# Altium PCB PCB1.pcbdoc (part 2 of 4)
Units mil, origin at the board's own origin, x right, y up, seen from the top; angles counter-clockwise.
Board outline 4701.34 x 4268.46 mil, 2 copper layers (Top Layer, Bottom Layer); 341 components, 58 nets, 1384 pads, 312 vias.
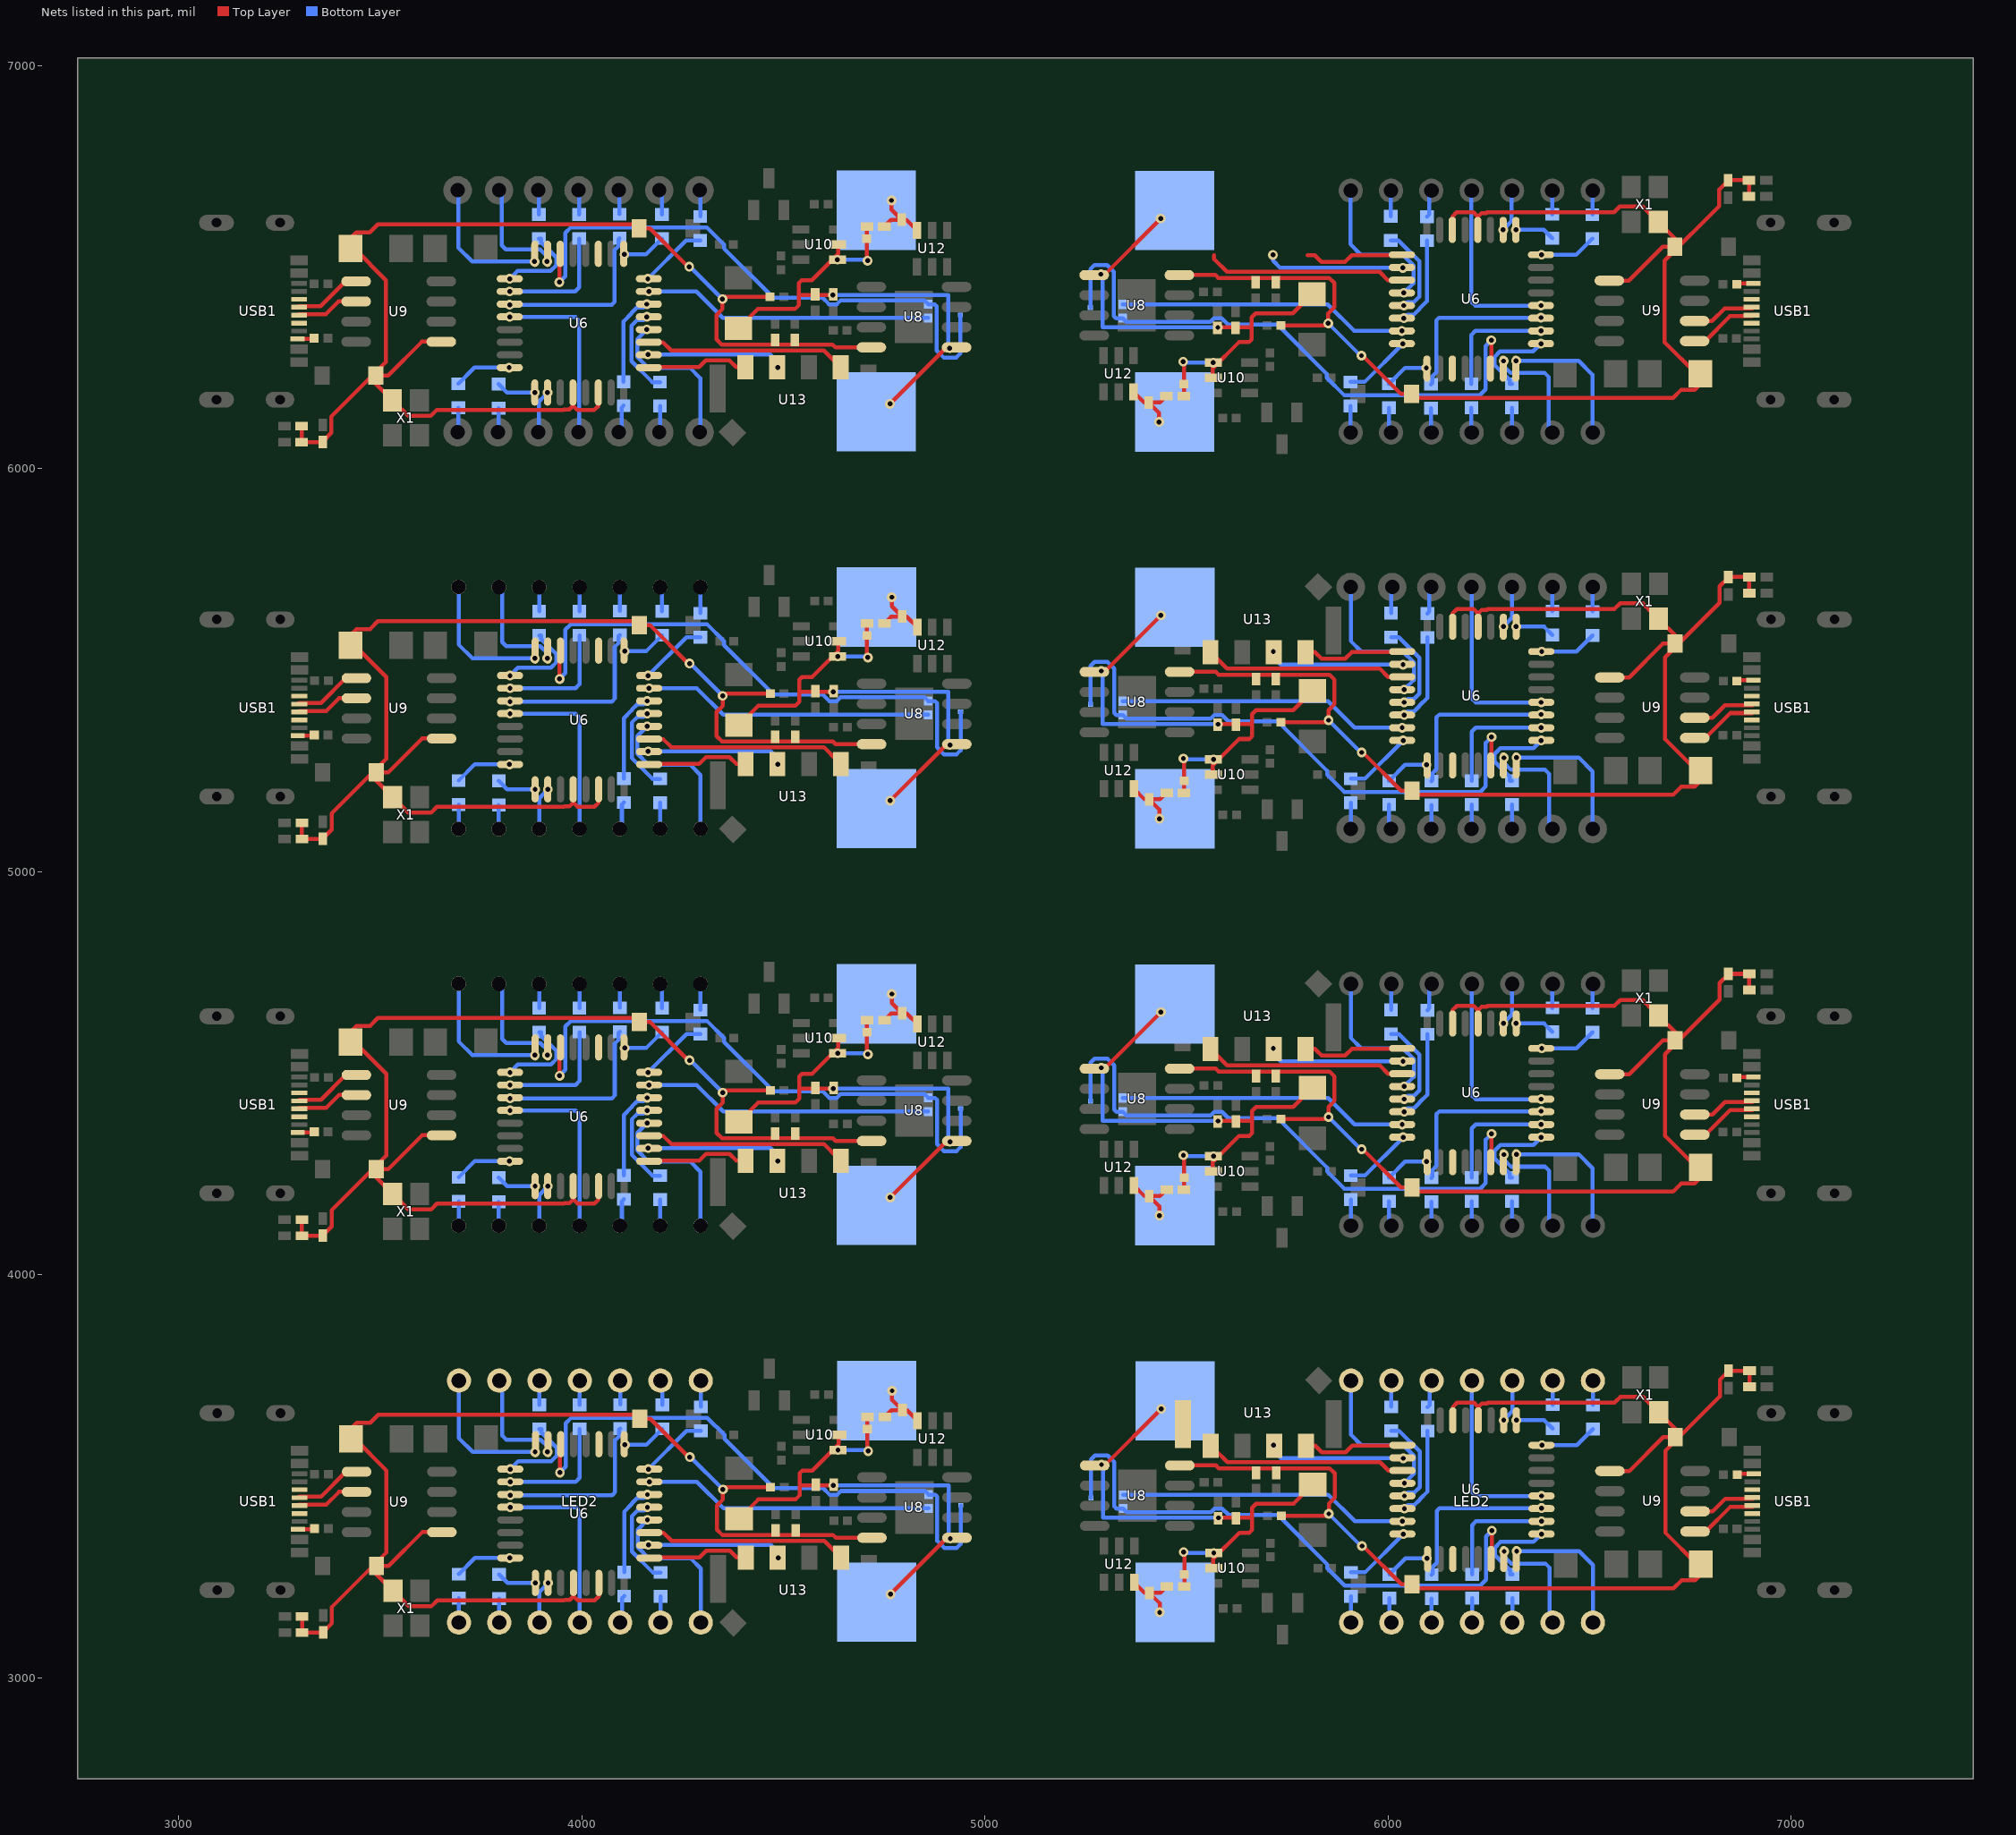
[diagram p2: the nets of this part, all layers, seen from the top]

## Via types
v1: diameter 24.02, hole 12.01, Top Layer to Bottom Layer, 312 vias

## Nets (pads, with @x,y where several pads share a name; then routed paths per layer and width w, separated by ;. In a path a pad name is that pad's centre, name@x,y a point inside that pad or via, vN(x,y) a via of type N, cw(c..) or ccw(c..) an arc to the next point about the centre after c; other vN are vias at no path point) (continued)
$1N14266: C24.2 C28.1 pad.73 pad.74 pad.75 pad.76 pad.77 pad.78 pad.79 pad.80 pad.81 pad.82 pad.83 pad.84 pad.85 pad.86 pad.88 pad.89 pad.91 pad.92 pad.93 pad.94 pad.95 pad.96 pad.97 pad.98 pad.100 pad.101 pad.102 pad.103 pad.104 pad.105 pad.106 pad.108 pad.124 pad.126 U12.6 | length 1259.3
  Top Layer w10: C28.1@4750.57,6600.59 4767.03,6617.05 C24.2@4794.11,6617.05 ; C28.1@4751.24,4632.09 4767.7,4648.55 C24.2@4794.78,4648.55 ; C28.1@4751.24,5616.34 4767.7,5632.8 C24.2@4794.78,5632.8 ; C28.1@4751.91,3647.83 4768.37,3664.29 C24.2@4795.45,3664.29 ; v1(4768.57,6665.07) 4768.57,6642.59 C24.2@4794.11,6617.05 ; v1(4769.24,4696.56) 4769.24,4674.09 C24.2@4794.78,4648.55 ; v1(4769.24,5680.81) 4769.24,5658.34 C24.2@4794.78,5632.8 ; v1(4769.91,3712.31) 4769.91,3689.83 C24.2@4795.45,3664.29 ; U12.6@4831.71,6590.83 4805.49,6617.05 C24.2@4794.11,6617.05 ; U12.6@4832.38,4622.33 4806.16,4648.55 C24.2@4794.78,4648.55 ; U12.6@4832.38,5606.58 4806.16,5632.8 C24.2@4794.78,5632.8 ; U12.6@4833.05,3638.07 4806.83,3664.29 C24.2@4795.45,3664.29 ; U12.6@5369.12,6189.84 5395.34,6163.62 C24.2@5406.72,6163.62 ; U12.6@5369.78,4221.34 5396,4195.12 C24.2@5407.38,4195.12 ; U12.6@5369.78,5205.59 5396,5179.37 C24.2@5407.38,5179.37 ; U12.6@5370.45,3237.09 5396.67,3210.87 C24.2@5408.05,3210.87 ; v1(5432.26,6115.61) 5432.26,6138.08 C24.2@5406.72,6163.62 ; v1(5432.92,4147.1) 5432.92,4169.58 C24.2@5407.38,4195.12 ; v1(5432.92,5131.35) 5432.92,5153.83 C24.2@5407.38,5179.37 ; v1(5433.59,3162.85) 5433.59,3185.32 C24.2@5408.05,3210.87 ; C28.1@5450.26,6180.08 5433.8,6163.62 C24.2@5406.72,6163.62 ; C28.1@5450.92,4211.58 5434.46,4195.12 C24.2@5407.38,4195.12 ; C28.1@5450.92,5195.83 5434.46,5179.37 C24.2@5407.38,5179.37 ; C28.1@5451.59,3227.33 5435.13,3210.87 C24.2@5408.05,3210.87
$1N25004: R39.1 | length 573.8
  Bottom Layer w10: R39.1@4194.11,6155.25 4194.11,6090.59 4199.11,6085.59 ; R39.1@4194.78,4186.75 4194.78,4122.09 4199.78,4117.09 ; R39.1@4194.78,5171 4194.78,5106.34 4199.78,5101.34 ; R39.1@4195.45,3202.49 4195.45,3137.83 4200.45,3132.83 ; 6001.72,6695.08 6006.72,6690.08 R39.1@6006.72,6625.42 ; 6002.38,4726.58 6007.38,4721.58 R39.1@6007.38,4656.92 ; 6002.38,5710.83 6007.38,5705.83 R39.1@6007.38,5641.17 ; 6003.05,3742.33 6008.05,3737.33 R39.1@6008.05,3672.67
$1N25008: R40.1 | length 532.8
  Bottom Layer w10: R40.1@3793.87,6150.02 3793.87,6090.83 3799.11,6085.59 ; R40.1@3794.54,4181.52 3794.54,4122.33 3799.78,4117.09 ; R40.1@3794.54,5165.77 3794.54,5106.58 3799.78,5101.34 ; R40.1@3795.21,3197.27 3795.21,3138.08 3800.45,3132.83 ; 6401.72,6695.08 6406.96,6689.84 R40.1@6406.96,6630.65 ; 6402.38,4726.58 6407.63,4721.34 R40.1@6407.63,4662.14 ; 6402.38,5710.83 6407.63,5705.59 R40.1@6407.63,5646.4 ; 6403.05,3742.33 6408.29,3737.08 R40.1@6408.29,3677.89
$1N25012: R41.1 | length 579.3
  Bottom Layer w10: 4099.11,6085.59 4099.11,6150.93 R41.1@4104.11,6155.93 ; 4099.78,4117.09 4099.78,4182.43 R41.1@4104.78,4187.43 ; 4099.78,5101.34 4099.78,5166.68 R41.1@4104.78,5171.68 ; 4100.45,3132.83 4100.45,3198.17 R41.1@4105.45,3203.17 ; R41.1@6096.72,6624.74 6101.72,6629.74 6101.72,6695.08 ; R41.1@6097.38,4656.24 6102.38,4661.24 6102.38,4726.58 ; R41.1@6097.38,5640.49 6102.38,5645.49 6102.38,5710.83 ; R41.1@6098.05,3671.99 6103.05,3676.99 6103.05,3742.33
$1N25014: R45.2 | length 445.3
  Bottom Layer w10: R45.2@4198.87,6630.02 4198.87,6685.35 4199.11,6685.59 ; R45.2@4199.54,4661.52 4199.54,4716.84 4199.78,4717.09 ; R45.2@4199.54,5645.77 4199.54,5701.1 4199.78,5701.34 ; R45.2@4200.21,3677.27 4200.21,3732.59 4200.45,3732.83 ; 6001.72,6095.08 6001.96,6095.32 R45.2@6001.96,6150.65 ; 6002.38,4126.58 6002.63,4126.82 R45.2@6002.63,4182.14 ; 6002.38,5110.83 6002.63,5111.07 R45.2@6002.63,5166.4 ; 6003.05,3142.33 6003.29,3142.57 R45.2@6003.29,3197.89
$1N25016: R46.2 | length 499.3
  Bottom Layer w10: R46.2@4294.11,6625.25 4294.11,6680.59 4299.11,6685.59 ; R46.2@4294.78,4656.75 4294.78,4712.09 4299.78,4717.09 ; R46.2@4294.78,5641 4294.78,5696.34 4299.78,5701.34 ; R46.2@4295.45,3672.49 4295.45,3727.83 4300.45,3732.83 ; 5901.72,6095.08 5906.72,6100.08 R46.2@5906.72,6155.42 ; 5902.38,4126.58 5907.38,4131.58 R46.2@5907.38,4186.92 ; 5902.38,5110.83 5907.38,5115.83 R46.2@5907.38,5171.17 ; 5903.05,3142.33 5908.05,3147.33 R46.2@5908.05,3202.67
$1N25022: R43.2 | length 461.9
  Bottom Layer w10: R43.2@3993.87,6630.02 3993.87,6680.35 3999.11,6685.59 ; R43.2@3994.54,4661.52 3994.54,4711.84 3999.78,4717.09 ; R43.2@3994.54,5645.77 3994.54,5696.1 3999.78,5701.34 ; R43.2@3995.21,3677.27 3995.21,3727.59 4000.45,3732.83 ; 6201.72,6095.08 6206.96,6100.32 R43.2@6206.96,6150.65 ; 6202.38,4126.58 6207.63,4131.82 R43.2@6207.63,4182.14 ; 6202.38,5110.83 6207.63,5116.07 R43.2@6207.63,5166.4 ; 6203.05,3142.33 6208.29,3147.57 R43.2@6208.29,3197.89
$1N25024: R42.2 | length 463.7
  Bottom Layer w10: R42.2@3893.87,6630.02 3893.87,6689.55 ; R42.2@3894.54,4661.52 3894.54,4711.84 3899.78,4717.09 ; R42.2@3894.54,5645.77 3894.54,5696.1 3899.78,5701.34 ; R42.2@3895.21,3677.27 3895.21,3727.59 3900.45,3732.83 ; 6301.72,6095.08 6306.96,6100.32 R42.2@6306.96,6150.65 ; 6302.38,4126.58 6307.63,4131.82 R42.2@6307.63,4182.14 ; 6302.38,5110.83 6307.63,5116.07 R42.2@6307.63,5166.4 ; 6303.05,3142.33 6308.29,3147.57 R42.2@6308.29,3197.89
$1N25046: R44.1 | length 539.3
  Bottom Layer w10: R44.1@3694.11,6150.93 3694.11,6090.59 3699.11,6085.59 ; R44.1@3694.78,4182.43 3694.78,4122.09 3699.78,4117.09 ; R44.1@3694.78,5166.68 3694.78,5106.34 3699.78,5101.34 ; R44.1@3695.45,3198.17 3695.45,3137.83 3700.45,3132.83 ; 6501.72,6695.08 6506.72,6690.08 R44.1@6506.72,6629.74 ; 6502.38,4726.58 6507.38,4721.58 R44.1@6507.38,4661.24 ; 6502.38,5710.83 6507.38,5705.83 R44.1@6507.38,5645.49 ; 6503.05,3742.33 6508.05,3737.33 R44.1@6508.05,3676.99
$1N26871: R57.2 | length 453.8
  Bottom Layer w10: R57.2@4094.11,6630.93 4094.11,6680.59 4099.11,6685.59 ; R57.2@4094.78,4662.43 4094.78,4712.09 4099.78,4717.09 ; R57.2@4094.78,5646.68 4094.78,5696.34 4099.78,5701.34 ; R57.2@4095.45,3678.17 4095.45,3727.83 4100.45,3732.83 ; 6101.72,6095.08 6106.72,6100.08 R57.2@6106.72,6149.74 ; 6102.38,4126.58 6107.38,4131.58 R57.2@6107.38,4181.24 ; 6102.38,5110.83 6107.38,5115.83 R57.2@6107.38,5165.49 ; 6103.05,3142.33 6108.05,3147.33 R57.2@6108.05,3196.99
$1N29845: R52.2 USB1.B5 | length 337.9
  Top Layer w10: USB1.B5@3295.2,6321.39 3295.3,6321.29 3337.25,6321.29 R52.2@3337.16,6321.39 ; USB1.B5@3295.87,4352.88 3295.96,4352.78 3337.92,4352.78 R52.2@3337.82,4352.88 ; USB1.B5@3295.87,5337.13 3295.96,5337.04 3337.92,5337.04 R52.2@3337.82,5337.13 ; USB1.B5@3296.53,3368.63 3296.63,3368.53 3338.59,3368.53 R52.2@3338.49,3368.63 ; R52.2@6863.67,6459.29 6863.57,6459.38 6905.53,6459.38 USB1.B5@6905.63,6459.29 ; R52.2@6864.34,4490.78 6864.24,4490.88 6906.2,4490.88 USB1.B5@6906.3,4490.78 ; R52.2@6864.34,5475.03 6864.24,5475.13 6906.2,5475.13 USB1.B5@6906.3,5475.03 ; R52.2@6865.01,3506.53 6864.91,3506.63 6906.87,3506.63 USB1.B5@6906.96,3506.53
$1N31822: LED2.13
$1N31824: LED2.9
$1N31826: LED2.12
$1N31828: LED2.5
$1N31830: LED2.4
$1N31832: LED2.8
$1N31834: LED2.2
$1N31836: LED2.1
$1N31838: LED2.3
+5V: C19.2 C20.2 C21.1 C25.2 C27.2 D5.1 D6.1 L6.1 R53.2 U6.4 U6.6 U8.4 U9.5 X1.3 | length 25770.4
  Top Layer w10: C25.2@3305.57,6105.59 C21.1@3305.57,6065.59 C27.2@3357.65,6065.59 3357.65,6066.79 3379.26,6088.41 3379.26,6129.11 3514.68,6264.53 3514.68,6467.32 L6.1@3436.41,6545.59 ; C25.2@3306.24,4137.09 C21.1@3306.24,4097.09 C27.2@3358.32,4097.09 3358.32,4098.29 3379.93,4119.9 3379.93,4160.61 3515.35,4296.03 3515.35,4498.81 L6.1@3437.08,4577.09 ; C25.2@3306.24,5121.34 C21.1@3306.24,5081.34 C27.2@3358.32,5081.34 3358.32,5082.54 3379.93,5104.16 3379.93,5144.86 3515.35,5280.28 3515.35,5483.06 L6.1@3437.08,5561.34 ; C25.2@3306.91,3152.83 C21.1@3306.91,3112.83 C27.2@3358.99,3112.83 3358.99,3114.04 3380.6,3135.65 3380.6,3176.36 3516.02,3311.78 3516.02,3514.56 L6.1@3437.75,3592.83 ; L6.1@3426.41,6545.59 3426.41,6571.36 3441.02,6585.98 3474.5,6585.98 3494.11,6605.59 4132.48,6605.59 D5.1@4142.48,6595.59 4169.11,6595.59 4264.11,6500.59 v1(4266.86,6500.59) ; L6.1@3427.08,4577.09 3427.08,4602.86 3441.69,4617.47 3475.16,4617.47 3494.78,4637.09 4133.15,4637.09 D5.1@4143.15,4627.09 4169.78,4627.09 4264.78,4532.09 v1(4267.53,4532.09) ; L6.1@3427.08,5561.34 3427.08,5587.11 3441.69,5601.72 3475.16,5601.72 3494.78,5621.34 4133.15,5621.34 D5.1@4143.15,5611.34 4169.78,5611.34 4264.78,5516.34 v1(4267.53,5516.34) ; L6.1@3427.75,3592.83 3427.75,3618.61 3442.36,3633.22 3475.83,3633.22 3495.45,3652.83 4133.82,3652.83 D5.1@4143.82,3642.83 4170.45,3642.83 4265.45,3547.83 v1(4268.2,3547.83) ; U9.5@3651.89,6314.53 3603.66,6314.53 3519.72,6230.59 3485.74,6230.59 3485.74,6213.81 X1.3@3530.65,6168.9 3531.68,6168.9 3553.96,6146.62 3554.17,6146.62 3562.97,6137.82 3562.97,6136.79 3569.4,6130.36 3625.75,6130.36 3640.52,6145.13 3955.09,6145.13 3956.58,6146.62 3969.11,6146.62 3978.36,6155.87 ; U9.5@3652.55,4346.02 3604.33,4346.02 3520.39,4262.09 3486.41,4262.09 3486.41,4245.3 X1.3@3531.31,4200.4 3532.35,4200.4 3554.62,4178.12 3554.84,4178.12 3563.64,4169.32 3563.64,4168.29 3570.07,4161.85 3626.42,4161.85 3641.18,4176.62 3955.75,4176.62 3957.25,4178.12 3969.78,4178.12 3979.03,4187.37 ; U9.5@3652.55,5330.28 3604.33,5330.28 3520.39,5246.34 3486.41,5246.34 3486.41,5229.55 X1.3@3531.31,5184.65 3532.35,5184.65 3554.62,5162.37 3554.84,5162.37 3563.64,5153.57 3563.64,5152.54 3570.07,5146.11 3626.42,5146.11 3641.18,5160.87 3955.75,5160.87 3957.25,5162.37 3969.78,5162.37 3979.03,5171.62 ; U9.5@3653.22,3361.77 3604.99,3361.77 3521.06,3277.83 3487.08,3277.83 3487.08,3261.05 X1.3@3531.98,3216.14 3533.01,3216.14 3555.29,3193.87 3555.51,3193.87 3564.31,3185.07 3564.31,3184.03 3570.74,3177.6 3627.08,3177.6 3641.85,3192.37 3956.42,3192.37 3957.92,3193.87 3970.45,3193.87 3979.7,3203.12 ; U6.4@3978.36,6188.59 3978.36,6155.87 ; U6.4@3979.03,4220.09 3979.03,4187.37 ; U6.4@3979.03,5204.34 3979.03,5171.62 ; U6.4@3979.7,3235.83 3979.7,3203.12 ; U6.6@4041.35,6188.59 4041.35,6155.59 4030.89,6145.13 3989.11,6145.13 3978.36,6155.87 ; U6.6@4042.02,4220.09 4042.02,4187.09 4031.56,4176.62 3989.78,4176.62 3979.03,4187.37 ; U6.6@4042.02,5204.34 4042.02,5171.34 4031.56,5160.87 3989.78,5160.87 3979.03,5171.62 ; U6.6@4042.69,3235.83 4042.69,3202.83 4032.23,3192.37 3990.45,3192.37 3979.7,3203.12 ; R53.2@4467.07,6425.59 4354.11,6425.59 v1(4349.11,6420.59) 4349.11,6395.59 4334.11,6380.59 4334.11,6320.59 4347.03,6307.67 4622.03,6307.67 4629.11,6300.59 U8.4@4718.5,6300.59 ; R53.2@4467.74,4457.09 4354.78,4457.09 v1(4349.78,4452.09) 4349.78,4427.09 4334.78,4412.09 4334.78,4352.09 4347.7,4339.17 4622.7,4339.17 4629.78,4332.09 U8.4@4719.17,4332.09 ; R53.2@4467.74,5441.34 4354.78,5441.34 v1(4349.78,5436.34) 4349.78,5411.34 4334.78,5396.34 4334.78,5336.34 4347.7,5323.42 4622.7,5323.42 4629.78,5316.34 U8.4@4719.17,5316.34 ; R53.2@4468.41,3472.83 4355.45,3472.83 v1(4350.45,3467.83) 4350.45,3442.83 4335.45,3427.83 4335.45,3367.83 4348.36,3354.92 4623.36,3354.92 4630.45,3347.83 U8.4@4719.84,3347.83 ; U8.4@5482.33,6480.08 5571.72,6480.08 5578.8,6473 5853.8,6473 5866.72,6460.08 5866.72,6400.08 5851.72,6385.08 v1(5851.72,6360.08) 5846.72,6355.08 R53.2@5733.76,6355.08 ; U8.4@5482.99,4511.58 5572.38,4511.58 5579.47,4504.49 5854.47,4504.49 5867.38,4491.58 5867.38,4431.58 5852.38,4416.58 v1(5852.38,4391.58) 5847.38,4386.58 R53.2@5734.42,4386.58 ; U8.4@5482.99,5495.83 5572.38,5495.83 5579.47,5488.75 5854.47,5488.75 5867.38,5475.83 5867.38,5415.83 5852.38,5400.83 v1(5852.38,5375.83) 5847.38,5370.83 R53.2@5734.42,5370.83 ; U8.4@5483.66,3527.33 5573.05,3527.33 5580.14,3520.24 5855.14,3520.24 5868.05,3507.33 5868.05,3447.33 5853.05,3432.33 v1(5853.05,3407.33) 5848.05,3402.33 R53.2@5735.09,3402.33 ; v1(5933.96,6280.08) 5936.72,6280.08 6031.72,6185.08 D5.1@6058.35,6185.08 6068.35,6175.08 6706.72,6175.08 6726.33,6194.7 6759.8,6194.7 6774.42,6209.31 L6.1@6774.42,6235.08 ; v1(5934.63,4311.58) 5937.38,4311.58 6032.38,4216.58 D5.1@6059.01,4216.58 6069.01,4206.58 6707.38,4206.58 6727,4226.19 6760.47,4226.19 6775.08,4240.81 L6.1@6775.08,4266.58 ; v1(5934.63,5295.83) 5937.38,5295.83 6032.38,5200.83 D5.1@6059.01,5200.83 6069.01,5190.83 6707.38,5190.83 6727,5210.44 6760.47,5210.44 6775.08,5225.06 L6.1@6775.08,5250.83 ; v1(5935.3,3327.33) 5938.05,3327.33 6033.05,3232.33 D5.1@6059.68,3232.33 6069.68,3222.33 6708.05,3222.33 6727.67,3241.94 6761.14,3241.94 6775.75,3256.55 L6.1@6775.75,3282.33 ; U6.6@6159.47,6592.08 6159.47,6625.08 6169.94,6635.55 6211.72,6635.55 6222.46,6624.8 ; U6.6@6160.14,4623.58 6160.14,4656.58 6170.6,4667.04 6212.38,4667.04 6223.13,4656.29 ; U6.6@6160.14,5607.83 6160.14,5640.83 6170.6,5651.29 6212.38,5651.29 6223.13,5640.55 ; U6.6@6160.81,3639.33 6160.81,3672.33 6171.27,3682.79 6213.05,3682.79 6223.8,3672.04 ; U6.4@6222.46,6592.08 6222.46,6624.8 ; U6.4@6223.13,4623.58 6223.13,4656.29 ; U6.4@6223.13,5607.83 6223.13,5640.55 ; U6.4@6223.8,3639.33 6223.8,3672.04 ; U9.5@6548.94,6466.15 6597.17,6466.15 6681.11,6550.08 6715.09,6550.08 6715.09,6566.87 X1.3@6670.18,6611.77 6669.15,6611.77 6646.87,6634.05 6646.66,6634.05 6637.86,6642.85 6637.86,6643.88 6631.42,6650.32 6575.08,6650.32 6560.31,6635.55 6245.74,6635.55 6244.24,6634.05 6231.72,6634.05 6222.46,6624.8 ; U9.5@6549.61,4497.64 6597.84,4497.64 6681.77,4581.58 6715.75,4581.58 6715.75,4598.36 X1.3@6670.85,4643.27 6669.82,4643.27 6647.54,4665.55 6647.32,4665.55 6638.52,4674.34 6638.52,4675.38 6632.09,4681.81 6575.75,4681.81 6560.98,4667.04 6246.41,4667.04 6244.91,4665.55 6232.38,4665.55 6223.13,4656.29 ; U9.5@6549.61,5481.89 6597.84,5481.89 6681.77,5565.83 6715.75,5565.83 6715.75,5582.61 X1.3@6670.85,5627.52 6669.82,5627.52 6647.54,5649.8 6647.32,5649.8 6638.52,5658.6 6638.52,5659.63 6632.09,5666.06 6575.75,5666.06 6560.98,5651.29 6246.41,5651.29 6244.91,5649.8 6232.38,5649.8 6223.13,5640.55 ; U9.5@6550.28,3513.39 6598.51,3513.39 6682.44,3597.33 6716.42,3597.33 6716.42,3614.11 X1.3@6671.52,3659.02 6670.49,3659.02 6648.21,3681.29 6647.99,3681.29 6639.19,3690.09 6639.19,3691.12 6632.76,3697.56 6576.42,3697.56 6561.65,3682.79 6247.08,3682.79 6245.58,3681.29 6233.05,3681.29 6223.8,3672.04 ; L6.1@6764.42,6235.08 6686.14,6313.36 6686.14,6516.14 6821.56,6651.56 6821.56,6692.27 6843.18,6713.88 C27.2@6843.18,6715.08 C21.1@6895.26,6715.08 C25.2@6895.26,6675.08 ; L6.1@6765.08,4266.58 6686.81,4344.85 6686.81,4547.63 6822.23,4683.05 6822.23,4723.76 6843.84,4745.37 C27.2@6843.84,4746.58 C21.1@6895.92,4746.58 C25.2@6895.92,4706.58 ; L6.1@6765.08,5250.83 6686.81,5329.1 6686.81,5531.89 6822.23,5667.31 6822.23,5708.01 6843.84,5729.63 C27.2@6843.84,5730.83 C21.1@6895.92,5730.83 C25.2@6895.92,5690.83 ; L6.1@6765.75,3282.33 6687.48,3360.6 6687.48,3563.38 6822.9,3698.8 6822.9,3739.51 6844.51,3761.12 C27.2@6844.51,3762.33 C21.1@6896.59,3762.33 C25.2@6896.59,3722.33
  Bottom Layer w10: v1(4266.86,6500.59) 4269.11,6500.59 v1(4349.11,6420.59) ; v1(4267.53,4532.09) 4269.78,4532.09 v1(4349.78,4452.09) ; v1(4267.53,5516.34) 4269.78,5516.34 v1(4349.78,5436.34) ; v1(4268.2,3547.83) 4270.45,3547.83 v1(4350.45,3467.83) ; v1(5851.72,6360.08) 5931.72,6280.08 v1(5933.96,6280.08) ; v1(5852.38,4391.58) 5932.38,4311.58 v1(5934.63,4311.58) ; v1(5852.38,5375.83) 5932.38,5295.83 v1(5934.63,5295.83) ; v1(5853.05,3407.33) 5933.05,3327.33 v1(5935.3,3327.33)
A0: LED2.6 U6.23 | length 2223.2
  Bottom Layer w10: 3794.11,6690.59 3799.11,6690.59 3802.04,6687.66 3802.04,6553.84 3812.04,6543.84 3896.81,6543.84 3914.12,6526.54 v1(3914.12,6513.84) ; 3794.78,4722.09 3799.78,4722.09 3802.71,4719.16 3802.71,4585.34 3812.71,4575.34 3897.48,4575.34 3914.79,4558.03 v1(3914.79,4545.34) ; 3795.45,3737.83 3800.45,3737.83 3803.38,3734.9 3803.38,3601.09 3813.38,3591.09 3898.15,3591.09 3915.46,3573.78 v1(3915.46,3561.08) ; 3802.71,5703.41 3802.71,5569.59 3812.71,5559.59 3897.48,5559.59 3914.79,5542.28 v1(3914.79,5529.59) ; v1(6286.71,6266.83) 6286.71,6254.14 6304.01,6236.83 6388.79,6236.83 6398.79,6226.83 6398.79,6093.01 6401.72,6090.08 6406.72,6090.08 ; v1(6287.37,4298.33) 6287.37,4285.63 6304.68,4268.32 6389.45,4268.32 6399.45,4258.32 6399.45,4124.51 6402.38,4121.58 6407.38,4121.58 ; v1(6287.37,5282.58) 6287.37,5269.89 6304.68,5252.58 6389.45,5252.58 6399.45,5242.58 6399.45,5108.76 6402.38,5105.83 6407.38,5105.83 ; v1(6288.04,3314.08) 6288.04,3301.38 6305.35,3284.07 6390.12,3284.07 6400.12,3274.07 6400.12,3140.25 6403.05,3137.33 LED2.6@6408.05,3137.33
A1: LED2.7 U6.24 | length 2769.6
  Bottom Layer w10: 3694.11,6690.59 3694.11,6547.59 3728.36,6513.34 v1(3883.13,6513.34) ; 3694.78,4722.09 3694.78,4579.09 3729.03,4544.83 v1(3883.79,4544.83) ; 3694.78,5706.34 3694.78,5563.34 3729.03,5529.09 v1(3883.79,5529.09) ; 3695.45,3737.83 3695.45,3594.83 3729.7,3560.58 v1(3884.46,3560.58) ; v1(6317.7,6267.33) 6472.46,6267.33 6506.72,6233.08 6506.72,6090.08 ; v1(6318.37,4298.83) 6473.13,4298.83 6507.38,4264.58 6507.38,4121.58 ; v1(6318.37,5283.08) 6473.13,5283.08 6507.38,5248.83 6507.38,5105.83 ; v1(6319.04,3314.58) 6473.8,3314.58 6508.05,3280.33 LED2.7@6508.05,3137.33
A2: R42.1 U6.25 | length 1733.4
  Bottom Layer w10: v1(3821.61,6470.83) 3841.13,6490.35 3923.14,6490.35 3937.11,6504.32 3937.11,6523.36 3899.11,6561.37 3899.11,6570.59 3899,6570.7 R42.1@3893.87,6570.7 ; v1(3822.28,4502.32) 3841.8,4521.84 3923.81,4521.84 3937.78,4535.81 3937.78,4554.86 3899.78,4592.86 3899.78,4602.09 3899.67,4602.2 R42.1@3894.54,4602.2 ; v1(3822.28,5486.57) 3841.8,5506.09 3923.81,5506.09 3937.78,5520.06 3937.78,5539.11 3899.78,5577.11 3899.78,5586.34 3899.67,5586.45 R42.1@3894.54,5586.45 ; v1(3822.95,3518.07) 3842.47,3537.59 3924.48,3537.59 3938.45,3551.56 3938.45,3570.61 3900.45,3608.61 3900.45,3617.83 3900.33,3617.95 R42.1@3895.21,3617.95 ; R42.1@6306.96,6209.97 6301.83,6209.97 6301.72,6210.08 6301.72,6219.31 6263.71,6257.31 6263.71,6276.36 6277.68,6290.33 6359.7,6290.33 v1(6379.22,6309.85) ; R42.1@6307.63,4241.46 6302.5,4241.46 6302.38,4241.58 6302.38,4250.8 6264.38,4288.8 6264.38,4307.85 6278.35,4321.82 6360.36,4321.82 v1(6379.88,4341.34) ; R42.1@6307.63,5225.72 6302.5,5225.72 6302.38,5225.83 6302.38,5235.05 6264.38,5273.06 6264.38,5292.1 6278.35,5306.07 6360.36,5306.07 v1(6379.88,5325.59) ; R42.1@6308.29,3257.21 6303.17,3257.21 6303.05,3257.33 6303.05,3266.55 6265.05,3304.55 6265.05,3323.6 6279.02,3337.57 6361.03,3337.57 v1(6380.55,3357.09)
A3: R43.1 U6.26 | length 2383.3
  Bottom Layer w10: v1(3821.61,6439.33) 3984.11,6439.33 3993.87,6449.09 R43.1@3993.87,6570.7 ; v1(3822.28,4470.83) 3984.78,4470.83 3994.54,4480.58 R43.1@3994.54,4602.2 ; v1(3822.28,5455.08) 3984.78,5455.08 3994.54,5464.84 R43.1@3994.54,5586.45 ; v1(3822.95,3486.57) 3985.45,3486.57 3995.21,3496.33 R43.1@3995.21,3617.95 ; R43.1@6206.96,6209.97 6206.96,6331.58 6216.72,6341.34 v1(6379.22,6341.34) ; R43.1@6207.63,4241.46 6207.63,4363.08 6217.38,4372.84 v1(6379.88,4372.84) ; R43.1@6207.63,5225.72 6207.63,5347.33 6217.38,5357.09 v1(6379.88,5357.09) ; R43.1@6208.29,3257.21 6208.29,3378.83 6218.05,3388.59 v1(6380.55,3388.59)
A4: R57.1 U6.27 | length 3409.3
  Bottom Layer w10: v1(3821.61,6406.34) 4074.28,6406.34 4081.35,6413.41 4081.35,6542.11 4091.18,6551.94 4091.18,6568.68 R57.1@4094.11,6571.61 ; v1(3822.28,4437.83) 4074.95,4437.83 4082.02,4444.91 4082.02,4573.61 4091.85,4583.44 4091.85,4600.18 R57.1@4094.78,4603.11 ; v1(3822.28,5422.09) 4074.95,5422.09 4082.02,5429.16 4082.02,5557.86 4091.85,5567.69 4091.85,5584.43 R57.1@4094.78,5587.36 ; v1(3822.95,3453.58) 4075.62,3453.58 4082.69,3460.65 4082.69,3589.36 4092.52,3599.18 4092.52,3615.92 R57.1@4095.45,3618.85 ; R57.1@6106.72,6209.06 6109.64,6211.99 6109.64,6228.73 6119.47,6238.56 6119.47,6367.26 6126.54,6374.33 v1(6379.22,6374.33) ; R57.1@6107.38,4240.56 6110.31,4243.49 6110.31,4260.23 6120.14,4270.05 6120.14,4398.76 6127.21,4405.83 v1(6379.88,4405.83) ; R57.1@6107.38,5224.81 6110.31,5227.74 6110.31,5244.48 6120.14,5254.31 6120.14,5383.01 6127.21,5390.08 v1(6379.88,5390.08) ; R57.1@6108.05,3256.31 6110.98,3259.23 6110.98,3275.97 6120.81,3285.8 6120.81,3414.51 6127.88,3421.58 v1(6380.55,3421.58)
A5: LED2.11 U6.28 | length 3620.4
  Bottom Layer w10: v1(3821.61,6376.34) 3984.39,6376.34 3994.11,6366.62 3994.11,6090.59 ; v1(3822.28,4407.83) 3985.06,4407.83 3994.78,4398.11 3994.78,4122.09 ; v1(3822.28,5392.09) 3985.06,5392.09 3994.78,5382.37 3994.78,5106.34 ; v1(3822.95,3423.58) 3985.73,3423.58 3995.45,3413.86 3995.45,3137.83 ; 6206.72,6690.08 6206.72,6414.06 6216.44,6404.33 v1(6379.22,6404.33) ; 6207.38,4721.58 6207.38,4445.55 6217.1,4435.83 v1(6379.88,4435.83) ; 6207.38,5705.83 6207.38,5429.8 6217.1,5420.08 v1(6379.88,5420.08) ; LED2.11@6208.05,3737.33 6208.05,3461.3 6217.77,3451.58 v1(6380.55,3451.58)
A6: U6.19
A7: R22.1 R24.2 U6.22 | length 11965.8
  Top Layer w10: v1(3944.7,6462.32) 3944.7,6530.43 U6.22@3946.87,6532.59 ; v1(3945.37,4493.82) 3945.37,4561.92 U6.22@3947.53,4564.09 ; v1(3945.37,5478.07) 3945.37,5546.17 U6.22@3947.53,5548.34 ; v1(3946.04,3509.57) 3946.04,3577.67 U6.22@3948.2,3579.83 ; U6.22@6253.96,6248.08 6256.12,6250.25 v1(6256.12,6318.35) ; U6.22@6254.63,4279.58 6256.79,4281.74 v1(6256.79,4349.85) ; U6.22@6254.63,5263.83 6256.79,5265.99 v1(6256.79,5334.1) ; U6.22@6255.3,3295.33 6257.46,3297.49 v1(6257.46,3365.59)
  Bottom Layer w10: v1(3944.7,6462.32) 3959.11,6476.73 3959.11,6584.36 3973.22,6598.47 4272.47,6598.47 4272.55,6598.39 4310.07,6598.39 4352.86,6555.6 4352.86,6546.07 4475.13,6423.8 4597.33,6423.8 4613.5,6407.63 4632.54,6407.63 4641.52,6416.61 4850.13,6416.61 R24.2@4859.11,6407.63 4875.47,6407.63 4880.72,6402.37 4880.72,6292.57 4897.71,6275.59 4929.11,6275.59 4939.11,6285.59 R22.1@4939.11,6381.08 ; v1(3945.37,4493.82) 3959.78,4508.23 3959.78,4615.86 3973.89,4629.97 4273.14,4629.97 4273.22,4629.89 4310.74,4629.89 4353.53,4587.09 4353.53,4577.56 4475.8,4455.3 4597.99,4455.3 4614.16,4439.13 4633.21,4439.13 4642.19,4448.1 4850.8,4448.1 R24.2@4859.78,4439.13 4876.14,4439.13 4881.39,4433.87 4881.39,4324.07 4898.38,4307.09 4929.78,4307.09 4939.78,4317.09 R22.1@4939.78,4412.58 ; v1(3945.37,5478.07) 3959.78,5492.48 3959.78,5600.11 3973.89,5614.22 4273.14,5614.22 4273.22,5614.14 4310.74,5614.14 4353.53,5571.34 4353.53,5561.81 4475.8,5439.55 4597.99,5439.55 4614.16,5423.38 4633.21,5423.38 4642.19,5432.35 4850.8,5432.35 R24.2@4859.78,5423.38 4876.14,5423.38 4881.39,5418.12 4881.39,5308.32 4898.38,5291.34 4929.78,5291.34 4939.78,5301.34 R22.1@4939.78,5396.83 ; v1(3946.04,3509.57) 3960.45,3523.97 3960.45,3631.61 3974.55,3645.71 4273.81,3645.71 4273.89,3645.63 4311.4,3645.63 4354.2,3602.84 4354.2,3593.31 4476.47,3471.04 4598.66,3471.04 4614.83,3454.87 4633.88,3454.87 4642.86,3463.85 4851.47,3463.85 R24.2@4860.45,3454.87 4876.81,3454.87 4882.06,3449.62 4882.06,3339.82 4899.04,3322.83 4930.45,3322.83 4940.45,3332.83 R22.1@4940.45,3428.32 ; R22.1@5261.72,6399.59 5261.72,6495.08 5271.72,6505.08 5303.12,6505.08 5320.1,6488.1 5320.1,6378.3 5325.36,6373.04 R24.2@5341.72,6373.04 5350.69,6364.07 5559.31,6364.07 5568.28,6373.04 5587.33,6373.04 5603.5,6356.87 5725.7,6356.87 5847.96,6234.61 5847.96,6225.08 5890.76,6182.28 5928.27,6182.28 5928.35,6182.2 6227.61,6182.2 6241.72,6196.31 6241.72,6303.94 v1(6256.12,6318.35) ; R22.1@5262.38,4431.09 5262.38,4526.58 5272.38,4536.58 5303.79,4536.58 5320.77,4519.6 5320.77,4409.79 5326.03,4404.54 R24.2@5342.38,4404.54 5351.36,4395.56 5559.97,4395.56 5568.95,4404.54 5588,4404.54 5604.17,4388.37 5726.36,4388.37 5848.63,4266.1 5848.63,4256.57 5891.43,4213.78 5928.94,4213.78 5929.02,4213.7 6228.28,4213.7 6242.38,4227.81 6242.38,4335.44 v1(6256.79,4349.85) ; R22.1@5262.38,5415.34 5262.38,5510.83 5272.38,5520.83 5303.79,5520.83 5320.77,5503.85 5320.77,5394.05 5326.03,5388.79 R24.2@5342.38,5388.79 5351.36,5379.81 5559.97,5379.81 5568.95,5388.79 5588,5388.79 5604.17,5372.62 5726.36,5372.62 5848.63,5250.35 5848.63,5240.83 5891.43,5198.03 5928.94,5198.03 5929.02,5197.95 6228.28,5197.95 6242.38,5212.06 6242.38,5319.69 v1(6256.79,5334.1) ; R22.1@5263.05,3446.84 5263.05,3542.33 5273.05,3552.33 5304.46,3552.33 5321.44,3535.34 5321.44,3425.54 5326.69,3420.29 R24.2@5343.05,3420.29 5352.03,3411.31 5560.64,3411.31 5569.62,3420.29 5588.67,3420.29 5604.84,3404.11 5727.03,3404.11 5849.3,3281.85 5849.3,3272.32 5892.09,3229.53 5929.61,3229.53 5929.69,3229.45 6228.94,3229.45 6243.05,3243.55 6243.05,3351.18 v1(6257.46,3365.59)
BATT: C15.1 C16.1 C28.2 L3.1 pad.87 pad.90 pad.99 pad.107 pad.123 pad.125 R56.2 U8.5 U10.4 U10.5 U13.5@5491.04,3629.51 | length 9987.8
  Top Layer w10: L3.1@4389.11,6347.89 4436.81,6395.59 4529.11,6395.59 4539.11,6405.59 4539.11,6430.62 ; L3.1@4389.78,4379.39 4437.48,4427.09 4529.78,4427.09 4539.78,4437.09 4539.78,4462.12 ; L3.1@4389.78,5363.64 4437.48,5411.34 4529.78,5411.34 4539.78,5421.34 4539.78,5446.37 ; L3.1@4390.45,3395.13 4438.15,3442.83 4530.45,3442.83 4540.45,3452.83 4540.45,3477.87 ; v1(4623.02,6430.62) 4539.11,6430.62 ; v1(4623.69,4462.12) 4539.78,4462.12 ; v1(4623.69,5446.37) 4539.78,5446.37 ; v1(4624.36,3477.87) 4540.45,3477.87 ; U10.5@4636.01,6554.63 4636.01,6532.49 4570.81,6467.29 4545.81,6467.29 4539.11,6460.59 4539.11,6430.62 ; U10.5@4636.68,4586.13 4636.68,4563.99 4571.48,4498.78 4546.48,4498.78 4539.78,4492.09 4539.78,4462.12 ; U10.5@4636.68,5570.38 4636.68,5548.24 4571.48,5483.04 4546.48,5483.04 4539.78,5476.34 4539.78,5446.37 ; U10.5@4637.35,3601.88 4637.35,3579.74 4572.14,3514.53 4547.14,3514.53 4540.45,3507.83 4540.45,3477.87 ; C28.2@4707.65,6600.59 4707.07,6600.01 R56.2@4707.07,6570.59 4707.07,6517.63 v1(4709.11,6515.59) ; C28.2@4708.32,4632.09 4707.74,4631.51 R56.2@4707.74,4602.09 4707.74,4549.13 v1(4709.78,4547.09) ; C28.2@4708.32,5616.34 4707.74,5615.76 R56.2@4707.74,5586.34 4707.74,5533.38 v1(4709.78,5531.34) ; C28.2@4708.99,3647.83 4708.41,3647.25 R56.2@4708.41,3617.83 4708.41,3564.87 v1(4710.45,3562.83) ; v1(4764.72,6160.59) 4902.71,6298.58 v1(4912.82,6298.58) ; v1(4765.39,4192.09) 4903.38,4330.08 v1(4913.49,4330.08) ; v1(4765.39,5176.34) 4903.38,5314.33 v1(4913.49,5314.33) ; v1(4766.06,3207.83) 4904.05,3345.83 v1(4914.16,3345.83) ; v1(5288.01,6482.09) 5298.11,6482.09 v1(5436.11,6620.08) ; v1(5288.67,4513.59) 5298.78,4513.59 v1(5436.77,4651.58) ; v1(5288.67,5497.84) 5298.78,5497.84 v1(5436.77,5635.83) ; v1(5289.34,3529.33) 5299.45,3529.33 v1(5437.44,3667.33) ; v1(5491.72,6265.08) 5493.76,6263.04 R56.2@5493.76,6210.08 5493.76,6180.66 C28.2@5493.18,6180.08 ; v1(5492.38,4296.58) 5494.42,4294.54 R56.2@5494.42,4241.58 5494.42,4212.16 C28.2@5493.84,4211.58 ; v1(5492.38,5280.83) 5494.42,5278.79 R56.2@5494.42,5225.83 5494.42,5196.41 C28.2@5493.84,5195.83 ; v1(5493.05,3312.33) 5495.09,3310.29 R56.2@5495.09,3257.33 5495.09,3227.91 C28.2@5494.51,3227.33 ; U10.5@5564.81,6226.04 5564.81,6248.18 5630.02,6313.39 5655.02,6313.39 5661.72,6320.08 5661.72,6350.05 ; U10.5@5565.48,4257.53 5565.48,4279.67 5630.69,4344.88 5655.69,4344.88 5662.38,4351.58 5662.38,4381.55 ; U10.5@5565.48,5241.79 5565.48,5263.93 5630.69,5329.13 5655.69,5329.13 5662.38,5335.83 5662.38,5365.8 ; U10.5@5566.15,3273.28 5566.15,3295.42 5631.35,3360.63 5656.35,3360.63 5663.05,3367.33 5663.05,3397.29 ; v1(5577.81,6350.05) 5661.72,6350.05 ; v1(5578.47,4381.55) 5662.38,4381.55 ; v1(5578.47,5365.8) 5662.38,5365.8 ; v1(5579.14,3397.29) 5663.05,3397.29 ; L3.1@5811.72,6432.78 5764.02,6385.08 5671.72,6385.08 5661.72,6375.08 5661.72,6350.05 ; L3.1@5812.38,4464.28 5764.68,4416.58 5672.38,4416.58 5662.38,4406.58 5662.38,4381.55 ; L3.1@5812.38,5448.53 5764.68,5400.83 5672.38,5400.83 5662.38,5390.83 5662.38,5365.8 ; L3.1@5813.05,3480.03 5765.35,3432.33 5673.05,3432.33 5663.05,3422.33 5663.05,3397.29
  Bottom Layer w10: v1(4623.02,6430.62) 4909.11,6430.62 4909.11,6302.29 v1(4912.82,6298.58) ; v1(4623.69,4462.12) 4909.78,4462.12 4909.78,4333.79 v1(4913.49,4330.08) ; v1(4623.69,5446.37) 4909.78,5446.37 4909.78,5318.04 v1(4913.49,5314.33) ; v1(4624.36,3477.87) 4910.45,3477.87 4910.45,3349.54 v1(4914.16,3345.83) ; v1(4634.35,6518.19) 4706.51,6518.19 v1(4709.11,6515.59) ; v1(4635.02,4549.68) 4707.18,4549.68 v1(4709.78,4547.09) ; v1(4635.02,5533.93) 4707.18,5533.93 v1(4709.78,5531.34) ; v1(4635.69,3565.43) 4707.85,3565.43 v1(4710.45,3562.83) ; v1(5288.01,6482.09) 5291.72,6478.38 5291.72,6350.05 v1(5577.81,6350.05) ; v1(5288.67,4513.59) 5292.38,4509.88 5292.38,4381.55 v1(5578.47,4381.55) ; v1(5288.67,5497.84) 5292.38,5494.13 5292.38,5365.8 v1(5578.47,5365.8) ; v1(5289.34,3529.33) 5293.05,3525.62 5293.05,3397.29 v1(5579.14,3397.29) ; v1(5491.72,6265.08) 5494.31,6262.49 v1(5566.47,6262.49) ; v1(5492.38,4296.58) 5494.98,4293.98 v1(5567.14,4293.98) ; v1(5492.38,5280.83) 5494.98,5278.23 v1(5567.14,5278.23) ; v1(5493.05,3312.33) 5495.65,3309.73 v1(5567.81,3309.73)
D2: R44.2 U6.32 | length 1142
  Bottom Layer w10: R44.2@3694.11,6210.25 3734.21,6250.35 v1(3820.24,6250.35) ; R44.2@3694.78,4241.75 3734.88,4281.85 v1(3820.91,4281.85) ; R44.2@3694.78,5226 3734.88,5266.1 v1(3820.91,5266.1) ; R44.2@3695.45,3257.49 3735.55,3297.6 v1(3821.58,3297.6) ; v1(6380.58,6530.32) 6466.61,6530.32 R44.2@6506.72,6570.42 ; v1(6381.25,4561.81) 6467.28,4561.81 R44.2@6507.38,4601.92 ; v1(6381.25,5546.07) 6467.28,5546.07 R44.2@6507.38,5586.17 ; v1(6381.92,3577.56) 6467.95,3577.56 R44.2@6508.05,3617.67
D3: R40.2 U6.1 | length 788.8
  Bottom Layer w10: R40.2@3793.87,6209.34 3814.62,6188.59 v1(3883.87,6188.59) ; R40.2@3794.54,4240.84 3815.29,4220.09 v1(3884.54,4220.09) ; R40.2@3794.54,5225.09 3815.29,5204.34 v1(3884.54,5204.34) ; R40.2@3795.21,3256.59 3815.96,3235.83 v1(3885.21,3235.83) ; v1(6316.95,6592.08) 6386.2,6592.08 R40.2@6406.96,6571.33 ; v1(6317.62,4623.58) 6386.87,4623.58 R40.2@6407.63,4602.82 ; v1(6317.62,5607.83) 6386.87,5607.83 R40.2@6407.63,5587.08 ; v1(6318.29,3639.33) 6387.54,3639.33 R40.2@6408.29,3618.57
D4: LED2.10 U6.2 | length 854.5
  Bottom Layer w10: 3894.11,6090.59 3894.11,6166.31 3906.87,6179.07 3906.87,6180.09 v1(3915.37,6188.59) ; 3894.78,4122.09 3894.78,4197.81 3907.53,4210.56 3907.53,4211.58 v1(3916.04,4220.09) ; 3894.78,5106.34 3894.78,5182.06 3907.53,5194.81 3907.53,5195.83 v1(3916.04,5204.34) ; 3895.45,3137.83 3895.45,3213.55 3908.2,3226.31 3908.2,3227.33 v1(3916.71,3235.83) ; v1(6285.46,6592.08) 6293.96,6600.59 6293.96,6601.61 6306.72,6614.36 6306.72,6690.08 ; v1(6286.12,4623.58) 6294.63,4632.08 6294.63,4633.1 6307.38,4645.86 6307.38,4721.58 ; v1(6286.12,5607.83) 6294.63,5616.33 6294.63,5617.35 6307.38,5630.11 6307.38,5705.83 ; v1(6286.79,3639.33) 6295.3,3647.83 6295.3,3648.85 6308.05,3661.61 LED2.10@6308.05,3737.33
D5: U6.9 U13.4 | length 1991.1
  Top Layer w10: U6.9@4166.61,6250.35 4167.81,6251.56 4290.98,6251.56 4307.87,6268.45 4366.25,6268.45 4383.14,6251.56 U13.4@4401,6251.56 ; U6.9@4167.28,4281.85 4168.48,4283.05 4291.65,4283.05 4308.54,4299.94 4366.92,4299.94 4383.81,4283.05 U13.4@4401.67,4283.05 ; U6.9@4167.28,5266.1 4168.48,5267.3 4291.65,5267.3 4308.54,5284.19 4366.92,5284.19 4383.81,5267.3 U13.4@4401.67,5267.3 ; U6.9@4167.95,3297.6 4169.15,3298.8 4292.31,3298.8 4309.21,3315.69 4367.59,3315.69 4384.48,3298.8 U13.4@4402.34,3298.8 ; 5799.82,6529.12 5817.68,6529.12 5834.57,6512.23 5892.96,6512.23 5909.85,6529.12 6033.01,6529.12 U6.9@6034.22,6530.32 ; U13.4@5800.49,4560.61 5818.35,4560.61 5835.24,4543.72 5893.63,4543.72 5910.52,4560.61 6033.68,4560.61 U6.9@6034.88,4561.81 ; U13.4@5800.49,5544.86 5818.35,5544.86 5835.24,5527.97 5893.63,5527.97 5910.52,5544.86 6033.68,5544.86 U6.9@6034.88,5546.07 ; U13.4@5801.16,3576.36 5819.02,3576.36 5835.91,3559.47 5894.29,3559.47 5911.18,3576.36 6034.35,3576.36 U6.9@6035.55,3577.56
D6: U6.10 U13.3 | length 2749.3
  Bottom Layer w10: v1(4164.25,6282.97) 4467.99,6282.97 4486.18,6264.78 v1(4486.18,6250.59) ; v1(4164.91,4314.47) 4468.66,4314.47 4486.85,4296.27 v1(4486.85,4282.09) ; v1(4164.91,5298.72) 4468.66,5298.72 4486.85,5280.53 v1(4486.85,5266.34) ; v1(4165.58,3330.21) 4469.33,3330.21 4487.52,3312.02 v1(4487.52,3297.83) ; v1(5714.64,6530.08) 5714.64,6515.89 5732.84,6497.7 v1(6036.58,6497.7) ; v1(5715.31,4561.58) 5715.31,4547.39 5733.5,4529.2 v1(6037.25,4529.2) ; v1(5715.31,5545.83) 5715.31,5531.64 5733.5,5513.45 v1(6037.25,5513.45) ; v1(5715.98,3577.33) 5715.98,3563.14 5734.17,3544.95 v1(6037.92,3544.95)
D7: U6.11 U13.1 | length 3973.7
  Top Layer w10: U6.11@4166.61,6313.35 4201.35,6313.35 4222.11,6292.59 4600.59,6292.59 4632.22,6260.96 U13.1@4632.22,6251.56 ; U6.11@4167.28,4344.84 4202.02,4344.84 4222.78,4324.09 4601.25,4324.09 4632.89,4292.45 U13.1@4632.89,4283.05 ; U6.11@4167.28,5329.09 4202.02,5329.09 4222.78,5308.34 4601.25,5308.34 4632.89,5276.71 U13.1@4632.89,5267.3 ; U6.11@4167.95,3360.59 4202.69,3360.59 4223.44,3339.84 4601.92,3339.84 4633.56,3308.2 U13.1@4633.56,3298.8 ; 5568.6,6529.12 5568.6,6519.72 5600.24,6488.08 5978.72,6488.08 5999.47,6467.33 U6.11@6034.22,6467.33 ; U13.1@5569.27,4560.61 5569.27,4551.21 5600.91,4519.57 5979.39,4519.57 6000.14,4498.82 U6.11@6034.88,4498.82 ; U13.1@5569.27,5544.86 5569.27,5535.46 5600.91,5503.83 5979.39,5503.83 6000.14,5483.07 U6.11@6034.88,5483.07 ; U13.1@5569.94,3576.36 5569.94,3566.96 5601.58,3535.32 5980.05,3535.32 6000.81,3514.57 U6.11@6035.55,3514.57
D8: LED2.14 U6.12 | length 3117.8
  Bottom Layer w10: v1(4161.61,6344.84) 4137.63,6320.87 4137.63,6277.07 4164.7,6250 4268.37,6250 4294.11,6224.26 4294.11,6090.59 ; v1(4162.28,4376.34) 4138.3,4352.36 4138.3,4308.56 4165.37,4281.5 4269.04,4281.5 4294.78,4255.75 4294.78,4122.09 ; v1(4162.28,5360.59) 4138.3,5336.61 4138.3,5292.81 4165.37,5265.75 4269.04,5265.75 4294.78,5240.01 4294.78,5106.34 ; v1(4162.95,3392.09) 4138.97,3368.11 4138.97,3324.31 4166.04,3297.24 4269.71,3297.24 4295.45,3271.5 4295.45,3137.83 ; 5906.72,6690.08 5906.72,6556.41 5932.46,6530.67 6036.12,6530.67 6063.19,6503.61 6063.19,6459.81 v1(6039.22,6435.83) ; 5907.38,4721.58 5907.38,4587.91 5933.12,4562.17 6036.79,4562.17 6063.86,4535.1 6063.86,4491.3 v1(6039.88,4467.33) ; 5907.38,5705.83 5907.38,5572.16 5933.12,5546.42 6036.79,5546.42 6063.86,5519.35 6063.86,5475.55 v1(6039.88,5451.58) ; LED2.14@5908.05,3737.33 5908.05,3603.66 5933.79,3577.92 6037.46,3577.92 6064.53,3550.85 6064.53,3507.05 v1(6040.55,3483.07)
D9: R39.2 U6.13 | length 1817.6
  Bottom Layer w10: v1(4161.61,6376.34) 4153.11,6367.83 4137.09,6367.83 4123.62,6354.37 4123.62,6266.08 4175.13,6214.57 R39.2@4194.11,6214.57 ; v1(4162.28,4407.83) 4153.77,4399.33 4137.75,4399.33 4124.29,4385.86 4124.29,4297.58 4175.8,4246.07 R39.2@4194.78,4246.07 ; v1(4162.28,5392.09) 4153.77,5383.58 4137.75,5383.58 4124.29,5370.11 4124.29,5281.83 4175.8,5230.32 R39.2@4194.78,5230.32 ; v1(4162.95,3423.58) 4154.44,3415.08 4138.42,3415.08 4124.95,3401.61 4124.95,3313.33 4176.47,3261.81 R39.2@4195.45,3261.81 ; R39.2@6006.72,6566.1 6025.7,6566.1 6077.21,6514.59 6077.21,6426.31 6063.74,6412.84 6047.72,6412.84 v1(6039.22,6404.33) ; R39.2@6007.38,4597.6 6026.36,4597.6 6077.88,4546.09 6077.88,4457.8 6064.41,4444.33 6048.39,4444.33 v1(6039.88,4435.83) ; R39.2@6007.38,5581.85 6026.36,5581.85 6077.88,5530.34 6077.88,5442.05 6064.41,5428.59 6048.39,5428.59 v1(6039.88,5420.08) ; R39.2@6008.05,3613.35 6027.03,3613.35 6078.54,3561.83 6078.54,3473.55 6065.08,3460.08 6049.06,3460.08 v1(6040.55,3451.58)
D10: R41.2 U6.14 | length 1805.9
  Bottom Layer w10: R41.2@4104.11,6215.25 4104.11,6365.33 4123.62,6384.84 4123.62,6385.86 4137.09,6399.33 4153.23,6399.33 v1(4161.61,6407.71) ; R41.2@4104.78,4246.75 4104.78,4396.83 4124.29,4416.34 4124.29,4417.36 4137.75,4430.83 4153.9,4430.83 v1(4162.28,4439.21) ; R41.2@4104.78,5231 4104.78,5381.08 4124.29,5400.59 4124.29,5401.61 4137.75,5415.08 4153.9,5415.08 v1(4162.28,5423.46) ; R41.2@4105.45,3262.49 4105.45,3412.58 4124.95,3432.09 4124.95,3433.11 4138.42,3446.57 4154.56,3446.57 v1(4162.95,3454.96) ; v1(6039.22,6372.96) 6047.6,6381.34 6063.74,6381.34 6077.21,6394.81 6077.21,6395.83 6096.72,6415.34 R41.2@6096.72,6565.42 ; v1(6039.88,4404.45) 6048.27,4412.84 6064.41,4412.84 6077.88,4426.31 6077.88,4427.33 6097.38,4446.83 R41.2@6097.38,4596.92 ; v1(6039.88,5388.71) 6048.27,5397.09 6064.41,5397.09 6077.88,5410.56 6077.88,5411.58 6097.38,5431.09 R41.2@6097.38,5581.17 ; v1(6040.55,3420.2) 6048.93,3428.59 6065.08,3428.59 6078.54,3442.05 6078.54,3443.07 6098.05,3462.58 R41.2@6098.05,3612.67
D11: R24.1 U6.15 | length 5758
  Bottom Layer w10: v1(4166.61,6439.33) 4284.59,6439.33 4350.37,6373.55 R24.1@4859.11,6373.55 ; v1(4167.28,4470.83) 4285.25,4470.83 4351.03,4405.05 R24.1@4859.78,4405.05 ; v1(4167.28,5455.08) 4285.25,5455.08 4351.03,5389.3 R24.1@4859.78,5389.3 ; v1(4167.95,3486.57) 4285.92,3486.57 4351.7,3420.79 R24.1@4860.45,3420.79 ; R24.1@5341.72,6407.12 5850.46,6407.12 5916.24,6341.34 v1(6034.22,6341.34) ; R24.1@5342.38,4438.62 5851.13,4438.62 5916.91,4372.84 v1(6034.88,4372.84) ; R24.1@5342.38,5422.87 5851.13,5422.87 5916.91,5357.09 v1(6034.88,5357.09) ; R24.1@5343.05,3454.37 5851.8,3454.37 5917.58,3388.59 v1(6035.55,3388.59)
D12: R46.1 U6.16 | length 1355.7
  Bottom Layer w10: v1(4164.04,6470.83) 4259.15,6565.93 R46.1@4294.11,6565.93 ; v1(4164.71,4502.32) 4259.81,4597.43 R46.1@4294.78,4597.43 ; v1(4164.71,5486.57) 4259.81,5581.68 R46.1@4294.78,5581.68 ; v1(4165.38,3518.07) 4260.48,3613.17 R46.1@4295.45,3613.17 ; R46.1@5906.72,6214.74 5941.68,6214.74 v1(6036.78,6309.85) ; R46.1@5907.38,4246.24 5942.35,4246.24 v1(6037.45,4341.34) ; R46.1@5907.38,5230.49 5942.35,5230.49 v1(6037.45,5325.59) ; R46.1@5908.05,3261.99 5943.02,3261.99 v1(6038.12,3357.09)
D13: R45.1 U6.17 | length 875.1
  Bottom Layer w10: v1(4105.92,6531.02) 4159.18,6531.02 R45.1@4198.87,6570.7 ; v1(4106.59,4562.51) 4159.85,4562.51 R45.1@4199.54,4602.2 ; v1(4106.59,5546.76) 4159.85,5546.76 R45.1@4199.54,5586.45 ; v1(4107.26,3578.26) 4160.52,3578.26 R45.1@4200.21,3617.95 ; R45.1@6001.96,6209.97 6041.65,6249.66 v1(6094.9,6249.66) ; R45.1@6002.63,4241.46 6042.31,4281.15 v1(6095.57,4281.15) ; R45.1@6002.63,5225.72 6042.31,5265.41 v1(6095.57,5265.41) ; R45.1@6003.29,3257.21 6042.98,3296.9 v1(6096.24,3296.9)
D+: U9.1 USB1.A6 USB1.B6 | length 1377.1
  Top Layer w10: USB1.A6@3295.2,6400.13 3298,6402.93 3352.74,6402.93 3414.34,6464.53 U9.1@3440.67,6464.53 ; USB1.A6@3295.87,4431.62 3298.67,4434.42 3353.41,4434.42 3415.01,4496.02 U9.1@3441.33,4496.02 ; USB1.A6@3295.87,5415.87 3298.67,5418.67 3353.41,5418.67 3415.01,5480.28 U9.1@3441.33,5480.28 ; USB1.A6@3296.53,3447.37 3299.33,3450.17 3354.08,3450.17 3415.68,3511.77 U9.1@3442,3511.77 ; U9.1@6760.16,6316.15 6786.49,6316.15 6848.09,6377.75 6902.83,6377.75 USB1.A6@6905.63,6380.55 ; U9.1@6760.83,4347.64 6787.15,4347.64 6848.76,4409.24 6903.5,4409.24 USB1.A6@6906.3,4412.04 ; U9.1@6760.83,5331.89 6787.15,5331.89 6848.76,5393.49 6903.5,5393.49 USB1.A6@6906.3,5396.29 ; U9.1@6761.5,3363.39 6787.82,3363.39 6849.42,3424.99 6904.16,3424.99 USB1.A6@6906.96,3427.79
D-: U9.2 USB1.A7 USB1.B7 | length 1276.7
  Top Layer w10: USB1.A7@3295.2,6380.45 3297.99,6383.24 3365.85,6383.24 3397.14,6414.53 U9.2@3440.67,6414.53 ; USB1.A7@3295.87,4411.94 3298.66,4414.73 3366.52,4414.73 3397.81,4446.02 U9.2@3441.33,4446.02 ; USB1.A7@3295.87,5396.19 3298.66,5398.98 3366.52,5398.98 3397.81,5430.28 U9.2@3441.33,5430.28 ; USB1.A7@3296.53,3427.69 3299.32,3430.48 3367.19,3430.48 3398.48,3461.77 U9.2@3442,3461.77 ; U9.2@6760.16,6366.15 6803.68,6366.15 6834.97,6397.44 6902.84,6397.44 USB1.A7@6905.63,6400.23 ; U9.2@6760.83,4397.64 6804.35,4397.64 6835.64,4428.93 6903.51,4428.93 USB1.A7@6906.3,4431.72 ; U9.2@6760.83,5381.89 6804.35,5381.89 6835.64,5413.18 6903.51,5413.18 USB1.A7@6906.3,5415.97 ; U9.2@6761.5,3413.39 6805.02,3413.39 6836.31,3444.68 6904.17,3444.68 USB1.A7@6906.96,3447.47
